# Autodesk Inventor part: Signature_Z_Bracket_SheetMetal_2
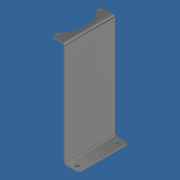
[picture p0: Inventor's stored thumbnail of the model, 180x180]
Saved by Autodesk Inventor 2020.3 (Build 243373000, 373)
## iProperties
Created: 2020-09
Part Number: Signature_Z_Bracket_SheetMetal_2
Material: Stainless Steel
Document SubType Name: Sheet Metal
Designer: BS
Manufacturer: Standard
Standards Organization: Custom
Density: 8 g/cm^3
Sheet Metal Rule: Default
Appearance: Semi-Polished
Author: BS
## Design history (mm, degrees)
derived "Signature_Measured.ipt"
  sketch "Sketch6"
    geometry: L1 (0, 0)-(-123.821, 0) reference; L2 (59, 0)-(-59, 0) reference; L3 (0, 0)-(7.279, 0) reference; L4 (7.279, -20)-(0, 0) reference; L5 (7.279, -20)-(7.279, 0) reference
  workplane "Work Plane1"
  workplane "Work Plane2"
  workaxis "Work Axis1"
  workpoint "Work Point1"
  workpoint "Work Point2"
  workpoint "Work Point3"
node "Contour Flange1"
  sketch "Sketch3"
    geometry: L1 (71, 170)-(-71, 170) reference; L2 (-40.962, 170)-(-70.962, 170); L3 (-70.962, 170)-(-70.962, -60); L4 (-70.962, -60)-(-100.962, -60); L5 (-42.712, 170)-(-42.712, 183) reference; L6 (-49.212, 170)-(-49.212, 183) reference; L7 (-42.712, 176.5)-(-49.212, 176.5); L8 (-45.962, 176.5)-(-45.962, 170); 1 further point
    constraints: 10 end point, 3 midpoint, 3 point on line, 2 perpendicular, 1 vertical
    dimensions: "d1" = 230 distance between parallel lines of L4 L1; "d2" = 30 distance of L3.end L4.end; "d3" = 30 distance from line of L3 L2.start; "d4" = 5 distance from line of L2.start L8
sketch "Sketch4"
  geometry: C1 r 59 at (40.962, 55) reference; C2 r 60 at (40.962, 55); C3 r 3.25 at (-5, 100.962) reference; C4 r 3.25 at (-5, 9.038) reference; 1 further point
  constraints: 1 centre point
  dimensions: "d16" = 1 radial gap between concentric circles of C1 C2
cut "Cut1" sketch "Sketch4" dims "d17" = 3.048 (= Thickness), "d18" = 0
sketch "Sketch5"
  geometry: L1 (-26.952, 110)-(-26.952, 0) reference; L2 (-26.952, 0)-(0, 0) reference; L3 (0, 0)-(0, 110) reference; L4 (-26.952, 110)-(0, 110) reference; L5 (-13.476, 100)-(-13.476, 10); L6 (0, 0)-(0, 110) reference; 4 further points
  constraints: 3 midpoint, 2 end point, 1 horizontal alignment, 1 vertical, 1 vertical alignment
  dimensions: "d19" = 90 distance of L5.start L5.end
hole "Hole1" sketch "Sketch5" at (-13.476, 10), (-13.476, 100) diameter "d20" = 10; stored, may be unused: countersink angle "d24" = 90 deg, drill point angle "d26" = 118 deg; dims "d21" = 6, "d22" = 4, "d23" = 2, "d25" = 3.048 (= Thickness)
feature "Corner Round1" dims "d27" = 6
body "Solid1"
tag "TaggingFeature1"
face "Plate1" dims "d5" = 3.048 (= Thickness), "d6" = 3.048 (= BendReliefWidth), "d7" = 1.524 (= BendReliefDepth), "d8" = 6.096 (= MinimumRemnant), "d9" = 3.048 (= TransitionRadius), "d10" = 110, "d11" = 3.048 (= BendRadius), "d12" = 3.048, "d13" = 12.192 (= CornerReliefSize), "d14" = 3.048 (= GapSize), "d15" = 3.048 (= JacobiRadiusSize), "SeamGap" = 0.01
bend "Bend1" dims "d5" = 3.048 (= Thickness), "d6" = 3.048 (= BendReliefWidth), "d7" = 1.524 (= BendReliefDepth), "d8" = 6.096 (= MinimumRemnant), "d9" = 3.048 (= TransitionRadius), "d11" = 3.048 (= BendRadius), "d12" = 3.048, "SeamGap" = 0.01
feature "Corner1" dims "d12" = 3.048, "d13" = 12.192 (= CornerReliefSize), "d14" = 3.048 (= GapSize), "d15" = 3.048 (= JacobiRadiusSize)
node "Projected Loop1"
feature "Solid1::Signature_Measured.ipt"
body "Srf1"
other parameters: "Thickness" = 3.048 (derived), "BendRadius" = 3.048 (= Thickness), "BendReliefWidth" = 3.048 (= Thickness), "BendReliefDepth" = 1.524 (= 0.5 x Thickness), "CornerReliefSize" = 12.192 (= 4 x Thickness), "MinimumRemnant" = 6.096 (= 2 x Thickness), "TransitionRadius" = 3.048 (= BendRadius), "JacobiRadiusSize" = 3.048 (= BendRadius), "GapSize" = 3.048 (= Thickness)
